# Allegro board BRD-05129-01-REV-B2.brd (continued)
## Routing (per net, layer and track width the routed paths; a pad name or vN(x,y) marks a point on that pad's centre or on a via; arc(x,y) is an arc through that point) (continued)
N1766806: length 1.6
  BOTTOM w0.203: R33.2 20.34,18.74 20.5,18.59 C37.1
N1766990: length 4.7
  TOP w0.203: v7(15.76,22.64) 15.76,23.86 16.56,24.66 17.1,24.66 Q21.2 17.35,25.03 17.31,25.07 R265.2
  BOTTOM w0.203: U6.7 v7(15.76,22.64)
N1767106: length 3.3
  BOTTOM w0.203: R32.2 17.14,20.38 17.59,19.93 C39.2 R30.2
  BOTTOM w0.254: R30.2 16.03,19.49 R31.1
N1767370: length 1.4
  BOTTOM w0.254: C319.2 23.19,18.59 R223.1
N2390901: length 3.5
  BOTTOM w0.13: R260.2 3.13,107.87 3.03,107.77 Q20.3 3.44,107.23 3.7,106.97 4.5,106.97 Q18.1
N2549814: length 1
  BOTTOM w0.13: C344.1 R264.2
N3548094: length 2.9
  BOTTOM w0.13: U38.35 29.38,93.06 28.36,92.04 R428.1
N3957555: length 2.5
  BOTTOM w0.13: R213.1 47.59,74.81 47.18,75.21 U37.24
N3957585: length 2.6
  BOTTOM w0.13: U37.22 47.38,76.21 47.9,75.69 R209.2
N3957595: length 2.8
  BOTTOM w0.13: C278.2 47.23,77.21 U37.20
N3957977: length 7.1
  BOTTOM w0.13: U43.54 61.98,86.91 61.22,86.15 60.83,86.15 60.34,85.66 59.93,85.66 59.44,85.17 59.44,84.88 C568.1 59.27,83.63 X13.1
N3957979: length 8.9
  BOTTOM w0.13: U43.53 62.38,86.82 61.34,85.78 60.97,85.78 60.53,85.33 60.26,85.33 60.15,85.22 C569.1 60.15,84.06 59.56,83.47 59.56,82.27 60.58,81.25 X13.3
N3958007: length 2.1
  BOTTOM w0.13: R468.1 64.78,96.63 U43.24
N3958011: length 2.3
  BOTTOM w0.13: R469.1 65.18,96.14 U43.25
N3958031: length 6.1
  BOTTOM w0.13: X12.3 47.07,70.65 C566.1 47.07,72.51 R467.1 46.25,73.33 45.51,73.33 44.88,73.96 44.88,74.51 U37.26
N3958033: length 9.1
  BOTTOM w0.13: X12.1 47.75,68.42 47.5,68.67 47.5,71.06 C567.1 47.96,71.52 R467.2 47.96,72.91 47.54,73.33 46.78,73.33 46.27,73.83 45.77,73.83 45.37,74.23 U37.25
N5304511: length 5.7
  BOTTOM w0.381: J24.9 66.86,103.33 C642.1
N5304817: length 4.2
  TOP w0.127: R537.2 58.48,95.45 60.19,93.74 60.19,93.49 60.42,93.26 U98.22
N5305693: length 1.5
  BOTTOM w0.13: R561.1 83.53,111.28 Q30.3
N5305711: length 4.2
  TOP w0.127: v1(68.08,95.03) 67.47,94.43 67.47,94.26 66.96,93.76 U98.10
  BOTTOM w0.13: R539.1 69.2,94.88 69.05,95.03 v1(68.08,95.03)
N5322338: length 5.3
  BOTTOM w0.381: C665.1 88.03,93.05 J25.P9_U
N5322486: length 3.9
  BOTTOM w0.13: R564.2 101.39,89.84 100.63,89.07 100.63,88.76 100.27,88.4 100.27,88.05 100.12,87.9 U99.22
N5323316: length 4.2
  BOTTOM w0.13: U99.10 93.55,88.4 92.83,89.13 92.83,89.31 92.07,90.07 91.46,90.07 91.05,89.65 R566.1
N5323550: length 0.9
  TOP w0.127: R578.1 Q32.3
N5323954: length 1.9
  TOP w0.127: R567.2 79.96,94 Q31.3 R577.1
N5327477: length 5.4
  BOTTOM w0.381: J25.P9_L 101.27,93.84 C687.1
N5327617: length 4.3
  TOP w0.127: R593.2 92.04,90.09 92.35,89.78 92.35,89.68 93.14,88.89 93.14,88.03 93.26,87.9 U101.22
N5328445: length 3.3
  TOP w0.127: U101.10 100.98,89.84 R595.1
N5328687: length 0.9
  TOP w0.127: R607.1 Q34.3
N5371142: length 2
  BOTTOM w0.13: R550.2 60.18,114.61 R551.1 Q29.3
N5372640: length 1.9
  TOP w0.127: R596.2 79.83,96.67 Q33.3 R606.1
N5400806: length 8.5
  BOTTOM w0.381: R520.1 128.51,84.08 130.38,82.22 132.51,82.22 134.03,83.74 J21.2
N5403476: length 2.6
  BOTTOM w0.381: R517.1 121.98,102.57 J19.2
N5403484: length 2.9
  BOTTOM w0.381: R518.1 117.9,103.57 J20.2
N5403540: length 7.3
  L03_SIG w0.254: v1(118.79,100.66) v1(118.79,101.67) 118.79,102.99 119.62,103.82 v1(119.62,105.19)
  BOTTOM w0.381: R517.2 v1(118.79,101.67) ; R518.2 v1(119.62,105.19) ; C601.1 v1(118.79,100.66)
N15688918: length 2
  TOP w0.127: DS10.2 v1(135.81,38.09)
  BOTTOM w0.13: DS10.2 v1(135.81,38.09)
N15743132: length 3.3
  TOP w0.203: v1(59.33,70.36) 59.09,70.6 R581.1
  BOTTOM w0.203: U100.7 58.65,71.04 v1(59.33,70.36)
N15988053: length 2.3
  BOTTOM w0.13: Q28.1 133.04,15.32 132.82,15.09 R532.1 R531.2
N15988135: length 0.8
  BOTTOM w0.13: R533.1 Q28.3
N15988139: length 1.6
  TOP w0.13: DS9.1 v1(134.29,16.56)
  BOTTOM w0.13: v1(134.29,16.56) 134.4,16.44 R533.2
N15991161: length 50.8
  L05_SIG w0.102: J23.1 28.75,17.16 28.75,20.37 29.13,20.75 29.13,22.78 28.44,23.46 28.44,35.17 v1(21.46,42.16)
  BOTTOM w0.13: R164.2 21.64,58.97 22.48,58.14 22.48,43.18 v1(21.46,42.16)
N15992386: length 7.2
  BOTTOM w0.381: J40.1 115.96,46.37 115.31,45.72 115.31,44.96 R660.2 115.27,44.9 R661.1 115.27,42.5 115.02,42.25 R662.1 Q44.3
N15992390: length 7.5
  L05_SIG w0.381: J41.1 117.19,28.3 v1(114.73,28.3)
  BOTTOM w0.381: R663.1 v1(114.73,28.3) 114.31,27.88 U113.5
N15992479: length 8.8
  TOP w0.254: C695.1 106.83,41.53 R624.1 106.85,41.04 v1(106.42,40.61) 106.6,40.43 U102.8
  L05_SIG w0.508: J26.1 106.02,40.61 v1(106.42,40.61)
  BOTTOM w0.381: R624.1 106.85,41.04 v1(106.42,40.61)
N15992497: length 8.8
  TOP w0.254: C702.1 106.83,58.42 R630.1 106.85,57.95 v1(106.4,57.5) 106.6,57.29 U103.8
  L05_SIG w0.508: J28.1 106.09,57.5 v1(106.4,57.5)
  BOTTOM w0.254: R630.1 106.85,57.95 v1(106.4,57.5)
N15992515: length 8.5
  TOP w0.254: C709.1 106.32,75.31 R636.1 106.35,74.64 v1(106.09,74.39) U104.8
  L05_SIG w0.508: v1(106.09,74.39) 103.78,74.39 J30.1
  BOTTOM w0.254: v1(106.09,74.39) 106.35,74.64 R636.1
N16064973: length 2.1
  BOTTOM w0.127: R528.1 R526.2
  BOTTOM w0.13: R526.2 73.05,23 R754.1
N16065039: length 2.6
  BOTTOM w0.381: Q24.1 76.33,20.91 C619.1 R528.2
N16065865: length 2.1
  BOTTOM w0.127: Q27.3 124.14,69.15 R527.2 R529.1
N16065931: length 2.6
  BOTTOM w0.381: Q25.1 126.67,70.17 C620.1 R529.2
N16074030: length 1.7
  BOTTOM w0.13: U19.5 R451.2
N16074034: length 1.9
  BOTTOM w0.13: U19.6 33.49,38.48 R450.2
N16074038: length 3
  BOTTOM w0.13: R449.2 31.42,38.73 31.42,39.67 32.01,40.27 U19.9
N16074042: length 2.1
  BOTTOM w0.13: R448.2 33.31,44.61 33.89,44.03 U19.20
N16074046: length 1.9
  BOTTOM w0.13: R447.2 34.2,44.38 34.29,44.28 U19.21
N16074090: length 2
  BOTTOM w0.13: R446.2 37.32,42.18 37.06,42.44 36.56,42.44 36.38,42.27 U19.27
N16074170: length 1.9
  BOTTOM w0.13: U91.2 70.77,80.33 70.55,80.12 R507.2
N16074248: length 1
  TOP w0.381: R54.2 29.27,22.24 ; C73.1 30.28,22.24
N16077585: length 1
  BOTTOM w0.13: R294.1 Q22.3
N16077589: length 2
  TOP w0.13: v1(2.25,37.84) 2.32,37.77 DS7.1
  BOTTOM w0.13: R294.2 2.44,37.66 v1(2.25,37.84)
N16077723: length 1.3
  BOTTOM w0.13: R295.1 3.72,33.96 Q23.3
N16077727: length 2
  TOP w0.13: v1(2.25,35.3) 2.32,35.23 DS8.1
  BOTTOM w0.13: v1(2.25,35.3) 2.44,35.12 R295.2
N16080552: length 1.2
  BOTTOM w0.13: Q6.3 R157.1
N16080556: length 2
  TOP w0.13: DS1.1 2.32,30.15 v1(2.25,30.22)
  BOTTOM w0.13: R157.2 2.44,30.04 v1(2.25,30.22)
N16080656: length 1
  BOTTOM w0.13: R254.1 Q17.3
N16080660: length 2
  TOP w0.13: v1(2.25,27.68) 2.32,27.61 DS6.1
  BOTTOM w0.13: R254.2 2.44,27.5 v1(2.25,27.68)
N16080760: length 1
  BOTTOM w0.13: R158.1 Q7.3
N16080764: length 2
  TOP w0.13: DS2.1 2.32,25.07 v1(2.25,25.14)
  BOTTOM w0.13: v1(2.25,25.14) 2.44,24.96 R158.2
N16080864: length 1
  BOTTOM w0.13: R159.1 Q8.3
N16080868: length 2
  TOP w0.13: DS3.1 2.32,22.53 v1(2.25,22.6)
  BOTTOM w0.13: v1(2.25,22.6) 2.44,22.42 R159.2
N16080968: length 1
  BOTTOM w0.13: R160.1 Q9.3
N16080972: length 2
  TOP w0.13: v1(2.25,20.06) 2.32,19.99 DS4.1
  BOTTOM w0.13: R160.2 2.44,19.88 v1(2.25,20.06)
N16081072: length 1
  BOTTOM w0.13: R161.1 Q10.3
N16081076: length 2
  TOP w0.13: DS5.1 2.32,17.45 v1(2.25,17.52)
  BOTTOM w0.13: v1(2.25,17.52) 2.44,17.34 R161.2
N16081750: length 1.5
  BOTTOM w0.13: U22.15 38.79,30.56 38.53,30.82 R66.1
N16081820: length 4
  TOP w0.127: X1.3 56.35,7.42 56.56,7.21 56.56,6.12 55.69,5.24 J4.4
N16081954: length 4.6
  TOP w0.254: 56.96,5.75 56.34,5.13 J4.5
  TOP w0.381: 56.96,5.75 57.85,6.64 L5.2 57.85,8.04 C88.2
N16082016: length 2.7
  TOP w0.127: v1(51.94,10.69) 52.36,11.11 R75.2
  BOTTOM w0.127: v1(51.94,10.69) 52.36,11.11 U24.14
N16082024: length 3.7
  TOP w0.127: R78.1 R74.2 v1(65.03,16.68)
  BOTTOM w0.13: U26.4 v1(65.03,16.68)
N16082026: length 14.6
  TOP w0.127: R76.2 v1(67.57,13.83)
  L03_SIG w0.102: v1(67.57,13.83) 67.07,13.33 61.31,13.33 59.68,14.96 v1(58.5,14.96)
  BOTTOM w0.127: U26.2 v1(67.57,13.83)
  BOTTOM w0.13: U24.62 v1(58.5,14.96)
N16082028: length 15.1
  TOP w0.13: R77.2 v1(68.84,13.83)
  L03_SIG w0.102: v1(59.24,14.46) 59.24,13.6 60.04,12.8 67.81,12.8 v1(68.84,13.83)
  BOTTOM w0.13: U26.1 v1(68.84,13.83) ; U24.63 v1(59.24,14.46)
N16082050: length 8.6
  TOP w0.127: R78.2 v1(66.3,13.83)
  L03_SIG w0.102: v1(62.25,15.01) 65.12,15.01 v1(66.3,13.83)
  BOTTOM w0.127: U26.3 v1(66.3,13.83)
  BOTTOM w0.13: U24.61 61.8,15.46 v1(62.25,15.01)
N16082060: length 6.1
  BOTTOM w0.13: C103.1 X2.1 60.35,9.53 59.35,9.53 58.36,10.52 U24.2
N16082074: length 9
  BOTTOM w0.13: U24.3 57.86,10.59 59.24,9.2 62.04,9.2 62.84,8.4 X2.3 C104.1
N16082098: length 2.7
  TOP w0.127: R79.2 56.31,13.2 v1(56,13.51)
  BOTTOM w0.13: U24.6 56.36,13.16 v1(56,13.51)
N16087534: length 0.9
  TOP w0.127: R274.1 C370.1
N16087546: length 0.9
  BOTTOM w0.13: R275.1 C371.1
N16095299: length 3.2
  TOP w0.381: U95.13 114.01,84.74 v1(113.58,85.18)
  BOTTOM w0.381: R534.1 114.01,84.74 v1(113.58,85.18)
N16189579:
  vias: v1(99.11,42.57) v1(100.38,42.57) v1(101.65,42.57)
N16189629:
  vias: v1(99.11,59.46) v1(101.65,59.46)
N16189705:
  vias: v1(97.18,73.81) v1(97.18,72.41) v1(101.34,72.49) v1(101.37,73.81)
N16192308: length 98.9
  TOP w0.127: Q37.1 v1(130.39,38.31)
  TOP w0.13: U104.7 106.59,74.08 v1(106.9,74.39) ; v1(107.41,57.5) 107.41,57.48 107.1,57.17 U103.7 ; U102.7 107.1,40.3 v1(107.41,40.61)
  L05_SIG w0.102: v1(107.41,40.61) 111.96,40.61 114.02,42.67 124.63,42.67 126.28,41.02 126.28,38.91 127.61,37.59 129.66,37.59 v1(130.39,38.31) 129.41,39.29 127.99,39.29 127.48,39.8 127.48,59.76 126.23,61.01 120.19,61.01 117.78,58.59 109.37,58.59 108.27,57.5 v1(107.41,57.5) 107.41,58.64 108.62,59.85 108.62,65.95 106.9,67.66 v1(106.9,74.39)
  BOTTOM w0.13: v1(107.41,40.61) R620.2 107.43,39.88 R623.1 C694.1
N16238907: length 2.8
  TOP w0.13: v1(113.58,94.23) 114.01,93.8 U95.8
  BOTTOM w0.13: R519.2 114.01,93.81 v1(113.58,94.23)
N17003721: length 3
  BOTTOM w0.254: R643.1 R642.1 126.41,44.08 126.41,44.8 126.44,44.83 TP41.1 126.44,45.38 126.41,45.41 R641.2
N17003765: length 4.3
  BOTTOM w0.254: R643.2 C722.1 124.75,42.09 124.75,42.09 U135.3
N17003879: length 4.4
  BOTTOM w0.254: R649.1 R648.1 118.19,59.14 117.94,58.88 TP43.1 R647.2
N17003923: length 4.2
  BOTTOM w0.254: R649.2 C731.1 U136.5
N17004020: length 3.1
  BOTTOM w0.254: R653.1 R652.1 131.25,63.62 TP45.1 131.83,63.62 131.84,63.62 R651.2
N17004081: length 4.3
  BOTTOM w0.254: R653.2 C742.1 129.2,61.7 U136.3
N17015726: length 5.1
  BOTTOM w0.254: U127.1 R63.2 74.34,48.82 R702.1
N17015844: length 5
  BOTTOM w0.254: U127.8 R64.2 74.32,54.89 R703.1
N17015909: length 5.1
  BOTTOM w0.254: R704.1 81.58,49.12 R58.2 U128.1
N17015913: length 23.1
  L12_SIG w0.254: v1(80.85,51.62) 80.52,51.96 80.03,51.96 79.68,51.61 79.68,48.41 78.52,47.26 75.98,47.26 70.94,42.21 67.64,42.21 v1(67.25,41.82)
  BOTTOM w0.254: v1(80.85,51.62) R704.2 U128.4 ; R740.1 v1(67.25,41.82)
N17016027: length 5
  BOTTOM w0.254: U128.8 R61.2 81.56,55.2 R705.1
N17016033: length 23
  L12_SIG w0.254: v1(67.25,42.96) 67.37,42.85 70.68,42.85 75.72,47.89 78.22,47.89 79.04,48.71 79.04,52.09 79.68,52.73 80.81,52.73 v1(80.85,52.77)
  BOTTOM w0.254: U128.5 R705.2 v1(80.85,52.77) ; R741.1 v1(67.25,42.96)
N17019057: length 5.1
  BOTTOM w0.254: U129.1 R707.2 74.34,57.77 R706.1
N17019061: length 12.4
  L12_SIG w0.254: v1(67.25,55.52) 69.34,57.62 72.27,57.62 73.62,58.96 v1(73.62,60.27)
  BOTTOM w0.254: v1(73.62,60.27) R706.2 U129.4 ; R742.1 v1(67.25,55.52)
N17019189: length 5
  BOTTOM w0.254: R709.1 74.32,63.84 R708.2 U129.8
N17019195: length 15.2
  L12_SIG w0.254: v1(67.25,54.38) 67.25,54.62 69.59,56.97 72.54,56.97 74.27,58.7 74.27,60.76 v1(73.62,61.41)
  BOTTOM w0.254: R743.1 v1(67.25,54.38) ; v1(73.62,61.41) R709.2 U129.5
N17019244: length 5.1
  BOTTOM w0.254: R710.1 81.58,58.07 R711.2 U130.1
N17019248: length 24.2
  L12_SIG w0.254: v1(80.85,60.57) 80.6,60.83 79.96,60.83 79.57,60.45 79.57,58.24 77.84,56.51 76.22,56.51 73.86,54.15 69.01,54.15 68.37,53.51 68.37,51.11 v1(67.25,49.99)
  BOTTOM w0.254: U130.4 R710.2 v1(80.85,60.57) ; R744.1 v1(67.25,49.99)
N17019376: length 5
  BOTTOM w0.254: U130.8 R712.2 81.56,64.15 R713.1
N17019382: length 23.8
  L12_SIG w0.254: v1(80.85,61.71) 80.83,61.69 79.9,61.69 78.89,60.68 78.89,58.57 77.46,57.14 75.95,57.14 73.6,54.78 68.74,54.78 67.74,53.78 67.74,51.62 v1(67.25,51.13)
  BOTTOM w0.254: R745.1 v1(67.25,51.13) ; U130.5 R713.2 v1(80.85,61.71)
N17020691: length 5.1
  BOTTOM w0.254: R714.1 74.34,66.71 R715.2 U131.1
N17020695: length 13.5
  L12_SIG w0.254: v1(67.25,63.69) 67.97,63.69 69.23,64.94 71.89,64.94 73.11,66.16 v1(73.11,69.21)
  BOTTOM w0.254: R746.1 v1(67.25,63.69) ; v1(73.11,69.21) 73.62,68.7 R714.2 U131.4
N17020826: length 5
  BOTTOM w0.254: U131.8 R716.2 74.32,72.79 R717.1
N17020832: length 16.1
  L12_SIG w0.254: v1(67.25,62.55) 67.69,62.99 68.17,62.99 69.49,64.31 72.16,64.31 73.74,65.89 73.74,69.72 v1(73.11,70.36)
  BOTTOM w0.254: v1(73.11,70.36) 73.62,70.86 R717.2 U131.5 ; R747.1 v1(67.25,62.55)
N17020881: length 5.1
  BOTTOM w0.254: R718.1 81.4,67.74 82.12,67.02 R719.2 U132.1
N17020885: length 24.4
  L12_SIG w0.254: v1(67.25,58.15) 68.25,59.15 68.25,60.96 68.98,61.69 72.41,61.69 75.87,65.15 78.23,65.15 79.73,66.65 79.73,69.26 80.23,69.77 80.6,69.77 v1(80.85,69.52)
  BOTTOM w0.254: R748.1 v1(67.25,58.15) ; U132.4 R718.2 v1(80.85,69.52)
N17021016: length 5
  BOTTOM w0.254: U132.8 R720.2 81.56,73.09 R721.1
N17021022: length 24
  L12_SIG w0.254: v1(80.85,70.66) 80.78,70.58 80.11,70.58 79.09,69.57 79.09,67 77.87,65.78 75.6,65.78 72.15,62.33 68.72,62.33 67.61,61.22 67.61,59.66 v1(67.25,59.3)
  BOTTOM w0.254: R749.1 v1(67.25,59.3) ; U132.5 R721.2 v1(80.85,70.66)
N17021071: length 5.1
  BOTTOM w0.254: U133.1 R723.2 74.34,39.87 R722.1
N17021075: length 12.4
  L12_SIG w0.254: v1(73.62,42.37) 73.62,40.53 71.84,38.76 67.68,38.76 v1(67.25,39.19)
  BOTTOM w0.254: R750.1 v1(67.25,39.19) ; U133.4 R722.2 v1(73.62,42.37)
N17021203: length 5
  BOTTOM w0.254: R725.1 74.32,45.95 R724.2 U133.8
N17021209: length 14.7
  L12_SIG w0.254: v1(73.62,43.52) 74.25,42.88 74.25,40.27 72.3,38.31 72.3,38.3 72.04,38.04 v1(67.25,38.04)
  BOTTOM w0.254: U133.5 R725.2 v1(73.62,43.52) ; R751.1 v1(67.25,38.04)
N17021264: length 5.1
  BOTTOM w0.254: R726.1 81.58,40.43 R727.2 U134.1
N17021268: length 22.9
  L12_SIG w0.254: v1(67.25,33.65) 67.5,33.9 71.9,33.9 75.89,37.89 77.82,37.89 79.52,39.59 79.52,42.87 79.8,43.15 80.64,43.15 v1(80.85,42.93)
  BOTTOM w0.254: U134.4 R726.2 v1(80.85,42.93) ; R752.1 v1(67.25,33.65)
N17021396: length 5
  BOTTOM w0.254: R729.1 81.56,46.51 R728.2 U134.8
N17021402: length 22.9
  L12_SIG w0.254: v1(80.85,44.08) 80.74,43.96 79.57,43.96 78.89,43.28 78.89,39.9 77.59,38.6 75.7,38.6 71.64,34.54 67.5,34.54 v1(67.25,34.79)
  BOTTOM w0.254: R753.1 v1(67.25,34.79) ; U134.5 R729.2 v1(80.85,44.08)
N17049267: length 4.7
  BOTTOM w0.13: U135.5 119.17,41.44 118.72,40.98 C758.1 R662.2
N17065894: length 11.4
  TOP w0.381: v1(69.58,41.62) 69.19,41.23 R737.2 R736.1 ; C809.1 70.23,36.87 v1(70.04,36.68)
  L10_SIG w0.381: v1(70.04,36.68) 68.63,38.1 68.63,40.66 69.58,41.61 v1(69.58,41.62)
  BOTTOM w0.381: v1(70.04,36.68) 70.23,36.87 C809.1 ; U137.5 v1(69.58,41.62)
N17098770: length 1.4
  TOP w0.127: Q37.3 DS10.1
N17140493: length 1.6
  BOTTOM w0.13: R754.2 72.11,22.49 71.99,22.36 Q26.3
N17244604: length 3.5
  BOTTOM w0.13: 113.33,41.66 R763.1 R762.2 Q43.3
N17444223: length 1.5
  TOP w0.13: D24.2 v1(38.19,17.31)
  BOTTOM w0.13: R267.2 v1(38.19,17.31)
N17444428: length 0.8
  TOP w0.13: D25.2 v1(45.13,17.4)

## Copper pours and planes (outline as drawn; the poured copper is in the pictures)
5V0_IN on TOP (solid shape): 27.25,28.14 27.25,25.22 27.22,25.21 27.07,25.09 26.99,24.91 26.99,24.86 21.18,24.86 19.78,26.26 19.78,28.44 20.05,28.71 26.68,28.71
5V0_IN on BOTTOM (solid shape): 113.98,89.49 113.98,88.58 113.72,88.32 112.59,88.32 112.38,88.52 112.38,89.65 112.42,89.68 113.79,89.68
5V0_IN on BOTTOM (solid shape): 6.71,73.9 6.71,71.13 6.58,71 4.77,71 4.77,72.44 4.76,72.6 4.61,72.75 4.61,74 4.8,74.2 6.41,74.2
5V0_IN on BOTTOM (solid shape): 71.75,19.12 71.75,17.28 71.09,17.28 71.01,17.26 70.93,17.22 69.69,17.22 69.46,17.45 69.46,18.74 70.1,19.37 71.49,19.37
5V0_IN on BOTTOM (solid shape): 31.39,82.18 31.39,81.32 31.6,81.11 33.43,81.11 33.72,80.82 36.08,80.82 36.13,80.76 36.13,79.58 35.9,79.35 30.21,79.35 29.93,79.63 29.93,82.25 29.98,82.3 31.27,82.3
5V0_IN on BOTTOM (solid shape): 66.56,25.14 66.56,24.73 67.53,23.76 68.19,23.76 68.7,24.28 68.7,25.49 68.95,25.49 68.95,25.49 68.95,24.37 69.18,24.15 69.18,23.52 68.84,23.18 66.63,23.18 65.86,23.95 64.6,23.95 64.43,24.11 64.43,25.77 65.93,25.77
5V0_IN on BOTTOM (solid shape): 125.25,72.22 125.25,70.75 125.07,70.56 124.44,70.56 124.26,70.48 124.19,70.3 124.19,69.81 122.87,69.81 122.87,72.27 125.2,72.27
5V0_IN on BOTTOM (solid shape): 27.25,28.09 27.25,25.25 27.22,25.23 27.05,25.11 26.97,24.92 26.96,24.88 21.02,24.88 19.24,26.66 19.24,27.04 18.81,27.57 18.81,27.59 18.79,27.71 18.73,27.82 18.73,28.56 18.86,28.69 26.65,28.69
5V0_IN on BOTTOM (solid shape): 9.9,44.56 8.03,44.56 7.9,44.69 7.52,44.69 7.44,44.8 7.44,45.43 7.35,45.52 7.27,45.58 7.18,45.58 6.43,45.58 6.38,45.58 6.36,45.57 6.23,45.48 6.18,45.33 6.18,44.75 6.12,44.69 6,44.68 5.66,44.68 5.54,44.8 5.54,46.35 5.91,46.73 9.9,46.73
5V0_IN on BOTTOM (solid shape): 5.25,54.15 5.25,53.99 5.21,53.91 5.19,53.83 5.19,53.13 5.21,53.04 5.25,52.96 5.25,52.6 5.61,52.24 6.63,52.24 6.78,52.09 6.78,51.99 6.28,51.99 6.1,51.92 6.03,51.74 6.03,51.23 6.1,51.05 6.28,50.97 6.78,50.97 6.78,49.14 6.65,49.02 4.01,49.02 4.01,52.17 4.09,52.24 4.17,52.24 4.19,52.27 4.72,52.27 4.92,52.47 4.92,53.01 4.95,53.07 4.95,53.13 4.95,54.2 4.97,54.22 5.18,54.22
5V0_IN on BOTTOM (solid shape): 29.45,83.53 29.45,77.83 29.18,77.56 26.56,77.56 26.51,77.61 26.51,78.89 26.63,79.01 27.48,79.01 27.7,79.22 27.7,79.93 28.18,79.93 28.18,79.88 28.19,79.82 28.21,79.77 28.24,79.73 28.27,79.68 28.31,79.65 28.35,79.61 28.4,79.59 28.45,79.57 28.51,79.56 28.56,79.56 28.61,79.57 28.66,79.58 28.71,79.6 28.76,79.63 28.8,79.66 28.84,79.7 28.87,79.75 28.89,79.8 28.91,79.85 28.91,79.9 28.91,79.96 28.91,80.01 28.89,80.06 28.87,80.11 28.84,80.15 28.8,80.19 28.76,80.23 28.71,80.26 28.66,80.28 28.61,80.29 28.56,80.3 28.51,80.3 28.45,80.29 28.4,80.27 28.35,80.24 28.31,80.21 28.27,80.18 28.24,80.13 28.21,80.09 28.19,80.04 28.18,79.98 28.18,79.93 27.7,79.93 27.7,81.05 27.99,81.34 27.99,83.17 27.87,83.29 27.83,83.31 27.78,83.33 27.73,83.34 27.71,83.34 26.66,83.34 26.66,83.51 27.46,83.51 27.46,83.52 27.77,83.52 27.91,83.66 27.96,83.66 27.96,83.71 28.01,83.76 29.22,83.76
5V0_IN on TOP: 43.38,93.26 43.38,91.18 42.74,90.55 39.75,90.55 39.32,90.98 39.32,92.45 39.52,92.65 40.64,92.65 41.27,93.29 43.35,93.29
5V0_IN on BOTTOM: 41.35,93.24 43.28,93.24 43.35,93.16 43.35,90.85 42.46,89.96 39.82,89.96 39.32,90.47 39.32,91.46 39.44,91.59 39.9,91.59 40.2,91.28 40.2,91.26 40.56,90.9 41.4,90.9 41.68,91.18 41.68,91.59 41.12,92.15 41.12,93.01
5V0_IN on L07_PWR: 1.27,114.05 2.35,116.65 4.95,117.73 60.93,117.72 60.93,116.45 83.54,116.45 83.54,117.72 86.65,117.72 86.65,117.21 87.25,115.77 88.68,115.18 101.39,115.18 102.83,115.77 103.42,117.21 103.42,117.72 135.05,117.71 137.65,116.63 138.73,114.03 138.73,65.91 90.88,65.91 89.71,64.74 89.71,28.06 87.7,26.06 87.7,1.28 4.95,1.27 2.35,2.35 1.27,4.95 ; 2 cut-outs
5V0_IN_SW on BOTTOM (solid shape): 21.4,23.99 25.84,23.99 26.35,23.48 26.35,21.21 25.89,20.74 23.61,20.74 22.79,19.92 22.75,19.91 22.72,19.92 22.64,19.97 22.54,19.99 22.03,19.99 21.93,19.97 21.85,19.92 21.78,19.89 21.71,19.92 21.62,19.97 21.53,19.99 21.02,19.99 20.84,19.92 20.76,19.74 20.76,19.25 20.58,19.25 20.43,19.4 20.43,20.9 19.62,21.71 19.62,23.36 18.86,24.12 17.72,24.12 17.59,24.25 17.97,24.63 19.24,24.63 19.37,24.75 20.64,24.75
5V0_RS485 on TOP (solid shape): 113.13,93.61 113.13,91.85 113.44,91.54 114.38,91.54 114.53,91.38 114.53,90.46 114.35,90.28 112.79,90.28 112.26,90.8 112.26,93.48 112.5,93.71 113.03,93.71
5V0_RS485 on BOTTOM (solid shape): 113.14,93.61 113.14,92 113.46,91.68 114.43,91.68 114.68,91.43 114.68,90.24 114.53,90.09 112.37,90.09 112.21,90.25 112.21,93.6 112.33,93.72 113.04,93.72
12V_IN on TOP (solid shape): 14.21,98.82 14.21,98.02 13.8,97.61 13.8,94.43 13.66,94.28 9.27,94.28 9.11,94.43 9.11,98.7 9.46,99.05 13.98,99.05
12V_IN on BOTTOM (solid shape): 14.67,24.5 15.81,24.5 16.45,23.86 17.46,23.86 17.46,23.61 15.94,23.61 14.29,21.96 10.03,21.96 9.8,22.19 9.8,24.38 10.05,24.63 14.54,24.63
12V_IN on BOTTOM: 74.67,22.77 74.69,22.74 75.3,22.74 75.61,22.44 77.08,22.44 77.13,22.49 77.13,23.4 76.83,23.71 76.83,24.19 76.72,24.29 76.19,24.29 75.96,24.52 75.96,25.16 75.71,25.41 74.82,25.41 74.67,25.26
12V_IN on L08_PWR: 1.27,116.3 1.91,117.11 2.73,117.75 26.41,117.75 26.41,31.8 28.52,29.69 28.52,16.86 28.16,16.51 1.27,16.51
12V_IN on L12_SIG: 77.85,25.01 77.85,3.27 75.87,1.29 14.63,1.29 9.75,6.17 9.75,24.63 10.31,25.19 19.15,25.19 21.81,22.53 21.81,18.97 31.24,9.55 63.32,9.55 69.62,15.85 69.62,25.19 70.28,25.85 77.01,25.85
12V_IN_JACK on TOP (solid shape): outline of 132 points within 13.25,95.26 20.97,109.27
12V_IN_JACK on BOTTOM (solid shape): outline of 106 points within 13.25,95.33 20.97,109.27
12V_IN_JACK on L03_SIG, L05_SIG, L12_SIG: 13.64,109.06 20.98,109.06 22.32,107.72 22.32,95.14 21.69,94.51 13.43,94.51 12.62,95.32 12.62,108.05
12V_IN_SOURCE on TOP (solid shape): 15.39,96.41 15.71,96.41 15.74,96.4 15.78,96.4 16.15,96.4 16.15,95.65 15.64,95.65 15.39,95.39 14.53,95.39 14.48,95.4 14.43,95.41 14.12,95.41 14.12,97.17 14.62,97.17
GND on TOP (solid shape): 7.59,44.14 7.59,42.92 7.37,42.7 6.26,42.7 6.02,42.94 6.02,44.13 6.25,44.36 7.37,44.36
GND on TOP (solid shape): 93.43,14.07 93.43,13.25 93.17,12.99 92.38,12.99 92.34,13 92.3,13 91.8,13 91.77,13 91.73,12.99 90.19,12.99 89.93,13.25 89.93,14.07 90.19,14.32 93.17,14.32
GND on TOP (solid shape): 104.69,72.06 104.83,72.06 104.89,72.04 104.94,72.03 105.24,72.03 105.3,72.04 105.36,72.06 105.83,72.06 105.89,72.04 105.94,72.03 107.03,72.03 107.18,71.88 107.18,69.9 106.98,69.69 105.89,69.69 104.84,70.74 103.44,70.74 103.23,70.95 101.88,70.95 101.88,71.95 102.76,72.84 103.91,72.84
GND on TOP (solid shape): 25.19,101.39 25.19,97.61 24.61,97.03 24.57,97.04 24.49,97.07 24.41,97.08 24.14,96.98 24.04,96.71 24.05,96.63 24.08,96.55 24.09,96.51 23.02,95.44 21.52,95.44 21.47,95.49 21.47,97.96 22.27,97.96 22.65,98.34 22.65,101.52 22.78,101.65 24.94,101.65
GND on TOP (solid shape): 105.2,55.17 105.33,55.17 105.37,55.15 105.41,55.14 105.45,55.14 105.75,55.14 105.79,55.14 105.83,55.15 105.87,55.17 106.28,55.17 106.29,55.16 106.36,55.16 106.41,55.14 106.45,55.14 107.57,55.14 107.71,55 107.71,52.87 107.56,52.72 106.11,52.72 106.01,52.82 106.01,52.83 106.04,52.91 106.05,53.01 106.04,53.09 106.01,53.17 106.01,53.19 106.01,53.4 105.55,53.85 103.9,53.85 103.69,54.06 102.36,54.06 102.36,55.67 102.63,55.95 104.42,55.95
GND on TOP (solid shape): 52.5,1.7 52.88,1.7 52.88,2.33 54.91,2.33 54.91,1.7 55.16,1.7 55.16,2.33 57.2,2.33 57.2,0.64 55.16,0.64 55.16,1.57 54.91,1.57 54.91,0.64 52.88,0.64 52.88,1.57 52.5,1.57 52.5,0.64 51.89,0.64 51.81,0.68 51.79,0.77 51.81,0.87 51.82,0.97 51.82,1.64 51.77,1.92 51.64,2.17 51.63,2.28 51.72,2.33 52.5,2.33
GND on TOP (solid shape): 105.2,38.28 105.33,38.28 105.37,38.26 105.41,38.25 105.45,38.25 105.75,38.25 105.79,38.25 105.83,38.26 105.87,38.28 106.33,38.28 106.37,38.26 106.4,38.25 106.46,38.22 106.49,38.15 106.49,38.15 106.85,37.78 107.22,38.15 107.25,38.22 107.32,38.25 107.58,38.25 107.84,37.99 107.84,37.35 107.14,36.65 106.04,36.65 105.73,36.96 103.97,36.96 103.77,37.17 102.36,37.17 102.36,38.78 102.63,39.06 104.42,39.06
GND on TOP (solid shape): outline of 229 points within 1.9,110.9 8.1,117.1
GND on TOP (solid shape): outline of 229 points within 1.9,1.9 8.1,8.1
GND on TOP (solid shape): outline of 229 points within 131.9,110.88 138.1,117.08
GND on TOP (solid shape): outline of 229 points within 131.9,1.91 138.1,8.12
GND on TOP (solid shape): outline of 238 points within 9.02,83.35 16.42,90.75
GND on TOP (solid shape): outline of 238 points within 9.02,29.7 16.42,37.1
GND on TOP (solid shape): outline of 238 points within 43.94,83.35 51.34,90.75
GND on TOP (solid shape): outline of 238 points within 43.94,29.7 51.34,37.1
GND on TOP (solid shape): outline of 238 points within 79.67,83.35 87.07,90.75
GND on TOP (solid shape): outline of 238 points within 79.67,29.7 87.07,37.1
GND on BOTTOM (solid shape): 111.94,89.56 111.94,88.47 111.69,88.22 110.55,88.22 110.37,88.4 110.37,89.62 110.43,89.68 111.82,89.68
GND on BOTTOM (solid shape): 42.59,13.42 42.34,13.17 42.34,11.9 42.21,11.77 40.48,11.77 40.41,11.85 40.41,12.92 40.79,13.3 40.81,13.3 40.94,13.42 40.94,15.71 41.07,15.84 42.59,15.84
GND on BOTTOM (solid shape): 4.43,72.39 4.43,70.8 4.59,70.64 4.59,69.45 4.4,69.26 2.82,69.26 2.64,69.43 2.64,70.76 2.77,70.87 2.82,71.04 2.82,72.44 4.38,72.44
GND on BOTTOM (solid shape): 4.77,62.58 4.77,59.25 4.59,59.08 2.76,59.08 2.49,58.8 2.49,55.98 2.66,55.8 4.09,55.8 4.19,55.7 4.19,52.62 4.06,52.5 3.53,52.5 3.35,52.32 3.35,49.07 3.3,49.02 1.06,49.02 0.68,49.4 0.68,62.53 0.86,62.71 4.64,62.71
GND on BOTTOM (solid shape): 74.36,28.67 74.36,26.28 71.01,26.28 70.65,26.64 70.65,27.83 70.52,27.96 69.08,27.96 68.92,27.8 68.92,26.51 68.9,26.48 68.42,26.48 68.29,26.61 68.29,27.75 68.16,27.88 65.93,27.88 65.75,27.7 65.75,26.46 65.67,26.38 64.33,26.38 64.27,26.43 64.27,28.49 64.85,29.06 73.96,29.06
GND on BOTTOM (solid shape): 25.87,87.72 25.87,85.59 25.52,85.23 24.33,85.23 24.2,85.11 24.2,83.66 24.35,83.51 25.65,83.51 25.67,83.48 25.67,83 25.54,82.87 24.4,82.87 24.27,82.74 24.27,80.19 24.64,79.83 25.13,79.83 25.13,79.29 25.2,79.11 25.38,79.04 25.87,79.04 25.87,77.68 25.81,77.62 23.48,77.62 22.9,78.2 22.9,86.35 24.3,87.75 25.85,87.75
GND on BOTTOM (solid shape): 40.12,84.5 40.12,82.96 40.1,82.93 37.96,82.93 37.61,83.29 37.61,84.48 37.48,84.61 36.03,84.61 35.88,84.45 35.88,83.16 35.86,83.13 35.37,83.13 35.25,83.26 35.25,84.4 35.12,84.53 32.57,84.53 32.2,84.17 32.2,83.68 31.67,83.68 31.49,83.6 31.41,83.42 31.41,82.93 30.05,82.93 29.99,82.99 29.99,85.32 30.57,85.9 38.72,85.9
GND on BOTTOM (solid shape): 59.99,64.54 62.53,64.54 62.75,64.32 62.75,53.74 62.75,53.72 62.75,44.51 62.75,43.34 62.75,33.16 62.51,32.91 59.64,32.91 59.61,32.94 59.61,32.94 58.97,32.94 58.97,32.94 58.97,37.73 58.99,37.75 58.97,37.77 58.97,46.75 58.99,46.77 58.97,46.79 58.97,64.3 59.23,64.56 59.99,64.56
GND on BOTTOM (solid shape): 26.46,19.96 26.46,18.08 26.46,18.08 26.46,17.89 26.21,17.64 25.05,17.64 25.04,17.65 24.96,17.68 24.87,17.69 24.78,17.68 24.7,17.65 24.69,17.64 24.54,17.64 24.45,17.73 24.45,17.93 24.48,18.01 24.57,18.03 24.61,18.03 25.59,18.03 25.77,18.1 25.84,18.28 25.84,19.6 25.77,19.78 25.59,19.85 24.61,19.85 24.56,19.85 24.51,19.83 24.45,19.83 24.45,19.93 24.74,20.22 26.21,20.22
GND on BOTTOM (solid shape): 5.79,44.41 5.86,44.38 5.93,44.37 6.18,44.37 6.25,44.38 6.31,44.41 6.37,44.38 6.43,44.37 6.68,44.37 6.75,44.38 6.81,44.41 6.87,44.38 6.93,44.37 7.68,44.37 7.73,44.38 7.78,44.39 7.81,44.4 7.9,44.31 9.84,44.31 10.11,44.05 10.11,42.93 9.83,42.66 7.78,42.66 7.73,42.68 7.68,42.68 5.93,42.68 5.88,42.68 5.83,42.66 5.56,42.66 5.49,42.59 5.49,41.11 4.71,41.11 4.66,41.11 4.61,41.1 4.52,41.11 4.47,41.19 4.47,44.11 4.78,44.42 5.78,44.42
GND on BOTTOM (solid shape): 64.42,77.63 64.42,76.3 64.41,76.29 64.38,76.23 64.37,76.16 64.37,75.86 64.38,75.81 64.4,75.76 64.38,75.71 64.37,75.66 64.37,75.36 64.38,75.31 64.4,75.26 64.38,75.21 64.37,75.16 64.37,74.36 64.38,74.3 64.41,74.24 64.42,74.22 64.42,74.07 64.67,73.82 66.84,73.82 66.96,73.7 66.96,73.61 66.44,73.61 66.26,73.54 66.19,73.36 66.19,72.85 66.26,72.67 66.44,72.59 66.96,72.59 66.96,72.22 66.78,72.04 63.87,72.04 62.64,73.27 62.64,74.22 62.65,74.23 62.67,74.29 62.68,74.36 62.68,74.66 62.68,74.71 62.66,74.76 62.68,74.81 62.68,74.86 62.68,75.16 62.68,75.21 62.66,75.26 62.68,75.31 62.68,75.36 62.68,75.66 62.68,75.71 62.66,75.76 62.68,75.81 62.68,75.86 62.68,76.15 62.76,76.23 62.76,77.63 62.89,77.76 64.29,77.76
GND on BOTTOM (solid shape): 55.55,78.35 55.55,76.98 55.54,76.97 55.51,76.91 55.5,76.84 55.5,76.54 55.51,76.49 55.52,76.44 55.51,76.39 55.5,76.34 55.5,76.04 55.51,75.99 55.52,75.94 55.51,75.89 55.5,75.84 55.5,75.04 55.51,74.97 55.54,74.91 55.55,74.9 55.55,74.8 55.8,74.54 57.33,74.54 57.33,73.97 57.4,73.79 57.58,73.71 58.09,73.71 58.09,73.01 56.23,73.01 56.15,73.04 56.07,73.05 55.99,73.04 55.91,73.01 55.63,73.01 54.83,73.81 54.83,73.81 54.76,73.88 53.92,73.88 53.77,74.04 53.77,74.9 53.78,74.91 53.8,74.97 53.81,75.04 53.81,75.34 53.81,75.39 53.79,75.44 53.81,75.49 53.81,75.54 53.81,75.84 53.81,75.89 53.79,75.94 53.81,75.99 53.81,76.04 53.81,76.34 53.81,76.39 53.79,76.44 53.81,76.49 53.81,76.54 53.81,76.87 53.9,76.96 53.9,78.35 54.02,78.48 55.42,78.48
GND on BOTTOM (solid shape): outline of 103 points within 118.03,5 124.2,17.97
GND on BOTTOM (solid shape): 26.35,30.38 26.35,29.33 26.22,29.2 18.86,29.2 17.84,28.18 17.84,27.55 17.27,27.55 17.09,27.47 17.02,27.29 17.02,26.78 17.09,26.6 17.27,26.53 17.84,26.53 17.84,26.02 18.03,25.83 18.03,25.01 15.94,25.01 15.78,24.85 14.68,24.85 14.65,24.88 14.54,24.88 14.25,25.17 9.9,25.17 9.34,24.61 9.34,22.04 9.93,21.45 14.29,21.45 14.39,21.34 14.38,21.31 14.36,21.25 14.35,21.19 14.35,20.68 14.38,20.57 14.45,20.48 14.5,20.41 14.47,20.33 14.43,20.25 14.41,20.17 14.41,19.79 14.42,19.74 14.43,19.69 14.43,19.61 14.37,19.56 14.24,19.47 14.2,19.32 14.2,18.81 14.27,18.63 14.45,18.55 14.73,18.55 14.82,18.49 14.81,18.39 14.26,17.77 11.76,17.77 8.45,21.08 8.45,27.71 8.89,28.14 15.44,28.14 18.21,30.91 25.82,30.91
GND on BOTTOM (solid shape): outline of 229 points within 1.9,110.9 8.1,117.1
GND on BOTTOM (solid shape): outline of 229 points within 1.9,1.9 8.1,8.1
GND on BOTTOM (solid shape): outline of 229 points within 131.9,110.88 138.1,117.08
GND on BOTTOM (solid shape): outline of 229 points within 131.9,1.91 138.1,8.11
GND on BOTTOM (solid shape): outline of 248 points within 9.02,83.35 16.42,90.75
GND on BOTTOM (solid shape): outline of 248 points within 9.02,29.7 16.42,37.1
GND on BOTTOM (solid shape): outline of 248 points within 43.94,83.35 51.34,90.75
GND on BOTTOM (solid shape): outline of 248 points within 43.94,29.7 51.34,37.1
GND on BOTTOM (solid shape): outline of 248 points within 79.67,83.35 87.07,90.75
GND on BOTTOM (solid shape): outline of 248 points within 79.67,29.7 87.07,37.1
GND on TOP: 89.61,65.32 92.88,65.32 92.88,29.23 91.89,28.24 91.89,20.52 92.5,19.91 97.28,19.91 97.99,20.62 104.82,20.62 104.82,19.35 105.08,19.1 111.48,19.1 112.29,18.28 112.29,13.99 112.24,13.93 109.37,13.93 108.41,14.9 105.8,14.9 105.27,15.43 105.27,16.23 104.69,16.81 96.95,16.81 96.19,17.57 90.45,17.57 86.76,21.26 86.76,28.95 89.2,31.39 89.2,64.92
GND on TOP: 102.9,86.54 104.1,86.54 104.56,86.08 104.56,83.6 104.22,83.27 102.86,83.27 102.86,86.5
GND on TOP: 110.01,61.56 113.38,61.56 113.38,59.97 113.1,59.68 110.18,59.68 110.01,59.86
GND on TOP: 128.98,29.51 123.21,29.51 122.55,30.17 122.55,33.07 122.6,33.07 126.41,36.88 138.05,36.88 139.37,35.56 139.37,19.5 138.53,18.66 130.12,18.66 129.49,19.3 129.49,29
GND on TOP: 63.51,45.91 63.51,43.34 63.45,43.29 62.33,43.29 62.15,43.47 62.15,45.57 62.5,45.92 63.5,45.92
GND on TOP: 109.5,78.45 112.87,78.45 112.87,76.86 112.59,76.58 109.68,76.58 109.5,76.75
GND on TOP: 63.51,54.08 63.51,51.51 63.45,51.45 62.33,51.45 62.15,51.63 62.15,53.74 62.5,54.09 63.5,54.09
GND on TOP: 12.62,99.64 13.93,99.64 14.08,99.79 14.08,100.95 13.7,101.33 12.66,101.33 12.56,101.23 12.56,99.7
GND on TOP: 110.01,44.67 113.38,44.67 113.38,43.07 113.1,42.79 110.18,42.79 110.01,42.97
GND on TOP: 63.51,62.25 63.51,59.68 63.45,59.62 62.33,59.62 62.15,59.8 62.15,61.9 62.5,62.25 63.5,62.25
GND on TOP: 124.2,17.77 124.2,12.75 122.75,11.3 122.75,5.28 122.09,4.62 118.79,4.62 118.26,5.15 118.26,10.31 119.11,11.16 119.11,17 119.93,17.83 124.15,17.83
GND on TOP: 66.7,98.95 67.88,98.95 67.96,98.87 67.96,97.53 65.7,97.53 65.7,98.07 65.71,98.08 66.31,98.08 66.56,98.33 66.56,98.81
GND on TOP: 63.51,37.74 63.51,35.18 63.45,35.12 62.33,35.12 62.15,35.3 62.15,37.4 62.5,37.75 63.5,37.75
GND on TOP: 43.4,93.8 43.4,95.12 42.78,95.73 38.64,95.73 38.43,95.52 38.43,93.83 39.17,93.09 40.47,93.09 41.18,93.8 43.39,93.8
GND on BOTTOM: 72.12,19.21 73.77,19.21 73.77,18.06 73.63,17.92 72.24,17.92 72.12,18.05
GND on BOTTOM: 89.61,65.32 93.16,65.32 94.03,64.46 94.03,29.6 92.19,27.76 92.19,20.47 92.62,20.05 96.25,20.05 98.64,22.44 109.56,22.44 109.9,22.78 112.31,22.78 112.44,22.65 112.44,13.51 112.31,13.38 110.13,13.38 109.52,13.99 104.8,13.99 103.63,15.16 103.63,15.34 102.15,16.81 96.95,16.81 95.99,17.77 88.93,17.77 86.79,19.91 86.79,28.98 89.2,31.39 89.2,64.92
GND on BOTTOM: 60.72,25.99 59.32,25.99 59.19,26.12 59.19,27.45 59.2,27.46 59.22,27.52 59.23,27.59 59.23,27.89 59.23,27.94 59.21,27.99 59.23,28.04 59.23,28.09 59.23,28.39 59.23,28.44 59.21,28.49 59.23,28.54 59.23,28.59 59.23,29.39 59.22,29.45 59.2,29.52 59.19,29.53 59.19,29.68 58.94,29.93 56.65,29.93 56.65,31.87 59.8,31.87 60.97,30.69 60.97,29.53 60.96,29.52 60.93,29.46 60.92,29.39 60.92,29.09 60.93,29.04 60.95,28.99 60.93,28.94 60.92,28.89 60.92,28.59 60.93,28.54 60.95,28.49 60.93,28.44 60.92,28.39 60.92,28.09 60.93,28.04 60.95,27.99 60.93,27.94 60.92,27.89 60.92,27.6 60.84,27.52 60.84,26.12
GND on BOTTOM: 128.85,29.33 123.39,29.33 122.55,30.17 122.55,35.45 123.23,36.13 125.64,36.13 126.38,36.88 138.05,36.88 139.37,35.56 139.37,19.5 138.53,18.66 130.12,18.66 129.49,19.3 129.49,28.7
GND on BOTTOM: 43.33,93.8 41.46,93.8 41.16,94.1 41.16,95.29 41.44,95.56 43.21,95.56 43.35,95.42 43.35,93.82
GND on BOTTOM: 90.4,86.98 90.4,83.21 90.27,83.08 88.41,83.08 88.06,83.42 88.06,84.88 88.57,85.38 88.57,87.09 88.77,87.3 90.08,87.3
GND on BOTTOM: 72.9,85.54 72.9,86.94 73.03,87.07 74.36,87.07 74.37,87.06 74.43,87.03 74.5,87.02 74.8,87.02 74.85,87.03 74.9,87.04 74.95,87.03 75,87.02 75.3,87.02 75.35,87.03 75.4,87.04 75.45,87.03 75.5,87.02 76.3,87.02 76.36,87.03 76.42,87.06 76.44,87.07 76.52,87.07 76.71,87.26 76.71,88.4 76.63,88.48 76.63,89.58 76.65,89.61 77.98,89.61 78.11,89.48 78.11,86.4 77.18,85.47 74.35,85.47 74.29,85.41 73.03,85.41
GND on BOTTOM: 80.42,5.13 72.31,5.13 70.61,6.83 70.61,9.32 69.87,10.05 67.86,10.05 67.23,10.69 67.23,13.2 67.43,13.41 68.83,13.41 69.31,13.89 72.34,13.89 75.46,10.77 80.03,10.77 81.45,9.35 81.45,6.15
GND on L02_GND: 139.37,4.96 138.1,1.91 135.05,0.65 108.59,0.65 108.59,0.64 86.98,0.64 4.95,0.63 1.9,1.9 0.64,4.95 0.64,114.05 1.9,117.1 4.95,118.36 61.57,118.36 61.57,117.08 82.9,117.08 82.9,118.35 87.29,118.35 87.29,117.21 87.53,116.42 88.18,115.9 88.18,114.63 90.14,114.63 90.14,115.81 99.56,115.81 99.56,114.55 102.13,114.55 102.13,115.95 101.99,115.95 102.57,116.46 102.79,117.21 102.79,118.35 135.05,118.35 138.1,117.08 139.37,114.03 ; 1 cut-out
GND on L04_GND, L06_GND, L09_GND, L11_GND: 139.37,4.96 138.1,1.91 135.05,0.65 4.95,0.63 1.9,1.9 0.64,4.95 0.64,114.05 1.9,117.1 4.95,118.36 61.57,118.36 61.57,117.08 82.9,117.08 82.9,118.35 87.29,118.35 87.29,117.21 87.53,116.42 88.18,115.9 88.18,114.63 90.14,114.63 90.14,115.81 99.56,115.81 99.56,114.55 102.13,114.55 102.13,115.95 101.99,115.95 102.57,116.46 102.79,117.21 102.79,118.35 135.05,118.35 138.1,117.08 139.37,114.03
GND on L05_SIG: 66.26,60.96 66.26,28.93 131.82,28.93 131.82,69.62 74.93,69.62
GND on L05_SIG: 73.17,12.85 66.24,19.78 66.24,21.28 64.82,22.7 55.44,22.7 53.56,24.58 53.56,26.74 51.18,29.13 45.89,29.13 39.54,35.48 38.1,35.48 37.18,36.39 36.32,36.39 35.99,36.06 35.99,35.05 37.46,33.57 39.65,33.57 41.3,31.92 41.3,29.87 43.43,27.73 50.14,27.73 51.43,26.44 51.43,22.37 55.62,18.18 61.57,18.18 69.01,10.74 71.7,10.74 73.17,12.21
GND on L10_SIG: 129.08,63.42 129.08,63.8 123.49,69.39 96.8,69.39 92.48,73.71 75.84,73.71 71.52,69.39 61.39,69.39 58.87,66.88 58.87,35.07 62.02,31.92 118.41,31.92 122.98,36.5 122.98,57.83 123.24,58.09 123.24,63.29 123.36,63.42
GND on L10_SIG: 11.65,54.05 11.65,51.18 12.62,50.21 17.04,50.21 18.21,51.38 20.21,51.38 22.22,49.38 22.22,46.6 28.15,40.67 29.38,40.67 32.18,37.87 35.54,37.87 35.83,37.57 35.83,34.8 36.34,34.29 37.45,34.29 37.83,34.67 37.83,40.85 35.27,43.41 32.49,43.41 31.42,44.48 31.42,45.64 28.5,48.56 26.16,48.56 21.38,53.34 17.45,53.34 16.73,54.05
GND on L12_SIG: 81.76,73.58 86.41,73.58 92.4,67.59 124.28,67.59 124.32,67.55 125.97,67.55 127.05,66.47 127.05,64.56 124.89,62.4 124.89,46.66 120.32,42.08 120.32,31.67 117.83,29.18 112.92,29.18 110.56,31.54 84.12,31.54 82.34,33.32 82.34,53.39 81.71,54.02 79.9,54.02 78.66,52.78 77.49,52.78 76.29,53.98 81.45,59.15 81.45,62.15 81.33,62.28 77.01,62.28 76.75,62.53 76.75,63.55 77.49,64.28 79.02,64.28 82.6,67.86 82.6,71.42 81.76,72.26
GND on L13_GND: 139.37,4.96 138.1,1.91 135.05,0.65 108.59,0.65 108.59,0.64 86.98,0.64 4.95,0.63 1.9,1.9 0.64,4.95 0.64,114.05 1.9,117.1 4.95,118.36 61.57,118.36 61.57,117.08 82.9,117.08 82.9,118.35 87.29,118.35 87.29,117.21 87.53,116.42 88.18,115.9 88.18,114.63 90.14,114.63 90.14,115.81 99.56,115.81 99.56,114.55 102.13,114.55 102.13,115.95 101.99,115.95 102.57,116.46 102.79,117.21 102.79,118.35 135.05,118.35 138.1,117.08 139.37,114.03
GND1_RS485 on TOP (solid shape): 111.79,93.67 111.79,90.96 111.67,90.84 110.51,90.84 110.34,91.02 110.34,93.51 110.55,93.72 111.74,93.72
GND1_RS485 on BOTTOM (solid shape): 111.84,93.61 111.84,90.15 111.78,90.09 110.37,90.09 110.17,90.29 110.17,93.52 110.31,93.67 111.78,93.67
GND1_RS485 on L03_SIG: 116.96,94.59 116.96,92.55 116.26,91.85 112.94,91.85 111.73,90.65 110.38,90.65 110.18,90.85 110.18,93.59 110.51,93.92 111.25,93.92 111.26,93.91 115.2,93.91 115.97,94.69 116.86,94.69
GND2_RS485 on TOP (solid shape): 111.81,81.07 111.68,80.95 110.54,80.95 110.41,81.07 110.41,84.25 110.54,84.37 111.81,84.37
GND2_RS485 on BOTTOM (solid shape): 111.93,84.12 111.93,81.71 111.81,81.58 110.41,81.58 110.41,84.25 110.54,84.37 111.68,84.37
(no net) on TOP: 111.81,84.37 111.81,81.07 111.68,80.95 110.54,80.95 110.41,81.07 110.41,84.25 110.54,84.37
(no net) on TOP: 57.7,18.08 57.7,16.3 57.5,16.09 57.5,14.76 57.96,14.3 57.96,13.57 57.69,13.31 56.72,13.31 56.13,13.9 56.13,18.03 56.3,18.21 57.58,18.21
(no net) on TOP: 104.25,65.86 101.88,65.86 101.35,65.32 97.96,65.32 97.23,66.06 97.23,69.67 101.07,69.67 101.07,67.27 101.45,66.9 104.26,66.9 104.38,66.79 104.38,65.98
(no net) on TOP: 102.47,86.55 102.47,83.41 102.44,83.38 101.56,83.38 101.13,83.81 101.13,84.19 100.63,84.69 100.63,85.07 100.82,85.26 101.03,85.26 101.27,85.51 101.27,86.33 101.49,86.55
(no net) on TOP: 116.8,82.62 115.05,82.62 114.97,82.69 114.97,84.41 114.35,85.03 114.35,86.87 114.5,87.01 115.44,87.01 115.68,86.78 115.68,85.48 116.83,84.33 116.83,82.65
(no net) on TOP: 106.67,61.44 106.67,60.66 106.61,60.6 105.78,60.6 105.33,60.16 105.33,57.23 105.7,56.86 105.7,55.44 105.28,55.44 105.17,55.56 105.17,56.47 104.55,57.08 104.55,60.73 105.26,61.44
(no net) on TOP: 113.03,84.43 112.34,84.43 112.23,84.32 112.23,80.45 112.28,80.39 113.64,80.39 113.91,80.67 113.91,82.22 113.83,82.3 113.44,82.3 113.1,82.64 113.1,84.35
(no net) on TOP: 102.36,36.56 105.45,36.56 105.76,36.25 105.76,35.67 105.71,35.59 105.7,35.5 105.7,34.12 102.5,34.12 102.18,34.44 102.18,35.25 102.36,35.43
(no net) on TOP: 63.96,54.12 64.61,54.12 64.97,53.77 65.1,53.77 65.39,53.48 65.39,51.92 64.94,51.46 64.04,51.46 63.92,51.59 63.92,54.08
(no net) on TOP: 112.23,79.99 113.49,79.99 113.66,79.82 113.66,79.05 113.36,78.75 112.41,78.75 112.23,78.93
(no net) on TOP: 109.06,77.07 109.06,78.5 108.89,78.67 106.83,78.67 106.57,78.41 106.57,77.54 106.65,77.45 107.75,77.45 108.14,77.07
(no net) on TOP: 59.74,16.56 59.74,19.6 59.61,19.73 58.59,19.73 58.34,19.48 58.34,16.56
(no net) on TOP: 102.18,53.45 105.25,53.45 105.76,52.94 105.76,52.56 105.71,52.48 105.7,52.39 105.7,51.01 102.5,51.01 102.18,51.33
(no net) on TOP: 117.7,5.25 117.7,10.94 118.31,11.55 118.31,16.96 118.11,17.17 113.46,17.17 113.15,16.86 113.15,12.31 112.11,11.27 112.11,4.57 112.57,4.11 116.56,4.11
(no net) on TOP: 111.59,80.44 111.59,79.12 111.45,78.98 110.28,78.98 110.05,79.21 110.05,80.31 110.27,80.53 111.51,80.53
(no net) on TOP: 105.25,72.33 105.25,73.68 104.82,74.12 104.82,77.05 105.27,77.5 106.1,77.5 106.16,77.55 106.16,78.43 105.99,78.6 105.03,78.6 104.05,77.62 104.05,73.97 104.66,73.36 104.66,72.44 104.76,72.33
(no net) on TOP: 106.67,44.55 106.67,43.77 106.61,43.71 105.78,43.71 105.33,43.26 105.33,40.34 105.7,39.97 105.7,38.55 105.28,38.55 105.17,38.67 105.17,39.07 104.24,40 104.24,42.34 104.52,42.62 104.52,43.81 105.36,44.65 106.57,44.65
(no net) on TOP: 102.63,55.95 104.42,55.95 105.2,55.17 105.33,55.17 105.4,55.15 105.45,55.14 105.75,55.14 105.8,55.15 105.87,55.17 106.28,55.17 106.29,55.16 107.56,55.16 107.71,55 107.71,52.87 107.56,52.72 106.11,52.72 106.01,52.82 106.01,53.4 105.55,53.85 103.9,53.85 103.69,54.06 102.36,54.06 102.36,55.67
(no net) on TOP: 90.1,16.12 93.23,16.12 93.48,15.86 93.48,15.01 93.23,14.75 90.1,14.75 89.84,15.01 89.84,15.86
(no net) on TOP: 13.98,99.05 9.46,99.05 9.11,98.7 9.11,94.43 9.27,94.28 13.66,94.28 13.8,94.43 13.8,97.61 14.21,98.02 14.21,98.82
(no net) on TOP: 63.96,62.29 64.77,62.29 65.41,61.65 65.41,60.01 65.03,59.63 64.04,59.63 63.92,59.75 63.92,62.24
(no net) on TOP: 98.62,32.48 98.62,37.51 101.52,37.51 101.52,33.83 102.15,33.2 105.2,33.2 105.2,32.48
(no net) on TOP: 104.74,70.34 101.67,70.34 101.67,68.23 101.99,67.9 105.22,67.9 105.25,67.93 105.25,69.83
(no net) on TOP: 118.1,82.64 117.45,82.64 117.33,82.76 117.33,84.48 116.69,85.12 116.69,86.59 116.95,86.85 117.54,86.85 118.13,86.27 118.13,82.67
(no net) on TOP: 20.05,28.71 26.68,28.71 27.25,28.14 27.25,24.86 21.18,24.86 19.78,26.26 19.78,28.44
(no net) on TOP: 102.07,42.81 102.07,39.82 98.62,39.82 98.62,42.71 98.88,42.97 101.92,42.97
(no net) on TOP: 111.74,93.72 110.55,93.72 110.34,93.51 110.34,91.02 110.51,90.84 111.67,90.84 111.79,90.96 111.79,93.67
(no net) on TOP: 102.07,59.7 102.07,56.71 98.62,56.71 98.62,59.61 98.88,59.86 101.92,59.86
(no net) on TOP: 113.03,93.71 112.5,93.71 112.26,93.48 112.26,90.8 112.79,90.28 114.35,90.28 114.53,90.46 114.53,91.38 114.38,91.54 113.44,91.54 113.13,91.85 113.13,93.61
(no net) on TOP: 101.88,70.95 103.23,70.95 103.44,70.74 104.84,70.74 105.89,69.69 106.98,69.69 107.18,69.9 107.18,71.88 107,72.06 104.69,72.06 103.91,72.84 102.76,72.84 101.88,71.95
(no net) on TOP: 48.43,12.24 46.78,12.24 46.53,11.98 46.53,10.46 46.66,10.33 47.29,10.33 47.92,10.97 48.43,10.97
(no net) on TOP: 23.02,95.44 21.52,95.44 21.47,95.49 21.47,97.96 22.27,97.96 22.65,98.34 22.65,101.52 22.78,101.65 24.94,101.65 25.19,101.39 25.19,97.61
(no net) on TOP: 50.19,8.23 53.31,8.23 53.51,8.43 53.51,9.57 53.26,9.83 50.85,9.83 50.19,9.16
(no net) on TOP: 50.34,3.22 59.76,3.22 59.76,0.64 50.34,0.64
(no net) on TOP: 20.84,95.26 20.97,95.4 20.97,105.17 20.97,105.17 20.97,108.92 20.62,109.27 14.02,109.27 13.25,108.5 13.25,102.99 14.9,101.34 17.87,101.34 18.08,101.14 18.08,97.07 17.57,96.57 16.4,96.57 16.4,95.39 16.53,95.26
(no net) on TOP: 108.64,60.18 108.26,60.56 107.16,60.56 107.08,60.65 107.08,61.52 107.34,61.78 109.4,61.78 109.57,61.61 109.57,60.18
(no net) on TOP: 64.94,35.25 63.92,35.25 63.92,37.74 64.84,37.74 65.44,37.15 65.44,35.75
(no net) on TOP: 98.62,49.2 98.62,54.4 101.39,54.4 101.77,54.02 101.77,50.47 101.88,50.36 104.8,50.36 105.03,50.14 105.03,49.2 104.77,48.94 98.88,48.94
(no net) on TOP: 113.93,95.58 113.93,96.98 113.76,97.15 112.88,97.15 112.64,96.91 112.64,95.67 112.83,95.49 113.84,95.49
(no net) on TOP: 63.92,45.91 63.92,43.42 64.04,43.29 64.66,43.29 64.76,43.39 65.02,43.39 65.4,43.77 65.4,45.37 64.82,45.95 63.96,45.95
(no net) on TOP: 6.02,44.13 6.02,42.94 6.26,42.7 7.37,42.7 7.59,42.92 7.59,44.14 7.37,44.36 6.25,44.36
(no net) on TOP: 114.35,96.37 114.35,95.59 113.93,95.16 113.93,94.35 114.17,94.11 115.01,94.11 115.24,94.33 115.24,95.26 115.49,95.51 115.49,96.37 115.35,96.51 114.5,96.51
(no net) on TOP: 92.55,83.92 92.76,84.12 92.76,84.88 92.63,85.01 91.61,85.01 91.49,84.88 91.49,83.99 91.56,83.92
(no net) on TOP: 53.89,3.48 53.89,5.63 54.15,5.89 54.15,7.16 54.4,7.41 54.4,7.92 54.66,8.17 55.42,8.17 55.55,8.3 55.55,9.19 55.42,9.32 54.53,9.32 53.77,8.56 53.77,7.79 53.64,7.67 52.62,7.67 52.62,6.52 53.51,5.63 53.51,3.48
(no net) on TOP: 108.64,43.29 108.26,43.67 107.16,43.67 107.08,43.75 107.08,44.63 107.34,44.88 109.4,44.88 109.57,44.71 109.57,43.29
(no net) on TOP: 102.63,39.06 104.42,39.06 105.2,38.28 105.33,38.28 105.4,38.26 105.45,38.25 105.75,38.25 105.8,38.26 105.87,38.28 107.56,38.28 107.84,37.99 107.84,37.35 107.14,36.65 106.04,36.65 105.73,36.96 103.97,36.96 103.77,37.17 102.36,37.17 102.36,38.78
(no net) on TOP: 96.57,72.16 96.57,73.91 96.74,74.09 101.6,74.09 101.7,73.99 101.7,72.36 101.16,71.83 96.9,71.83
(no net) on TOP: 90.19,14.32 93.17,14.32 93.43,14.07 93.43,13.25 93.17,12.99 90.19,12.99 89.93,13.25 89.93,14.07
(no net) on TOP: 15.64,95.65 15.39,95.39 14.12,95.39 14.12,97.17 14.62,97.17 15.39,96.41 16.26,96.41 16.26,95.77 16.13,95.65
(no net) on BOTTOM: 17.46,23.61 15.94,23.61 14.29,21.96 10.03,21.96 9.8,22.19 9.8,24.38 10.05,24.63 14.54,24.63 14.67,24.5 15.81,24.5 16.45,23.86 17.46,23.86
(no net) on BOTTOM: 26.35,30.38 26.35,29.33 26.22,29.2 18.86,29.2 17.84,28.18 17.84,26.02 18.1,25.77 18.1,25.01 15.94,25.01 15.78,24.85 14.57,24.85 14.25,25.17 9.9,25.17 9.34,24.61 9.34,22.04 9.93,21.45 14.29,21.45 14.54,21.2 15.05,21.2 15.05,20.52 14.99,20.47 14.68,20.47 14.54,20.32 14.54,19.57 14.65,19.46 14.99,19.46 15.05,19.4 15.05,18.66 14.26,17.77 11.76,17.77 8.45,21.08 8.45,27.71 8.89,28.14 15.44,28.14 18.21,30.91 25.82,30.91
(no net) on BOTTOM: 62.13,78.01 60.73,78.01 60.1,77.38 60.1,75.16 61.37,75.16 61.37,75.6 61.5,75.73 61.55,75.8 61.68,75.87 61.73,75.87 62.38,75.87 62.38,77.76
(no net) on BOTTOM: 33.72,80.82 33.43,81.11 31.6,81.11 31.39,81.32 31.39,82.18 31.27,82.3 29.98,82.3 29.93,82.25 29.93,79.63 30.21,79.35 35.9,79.35 36.13,79.58 36.13,80.76 36.08,80.82
(no net) on BOTTOM: 75.19,88.87 74.81,88.49 74.81,88.15 74.76,88.07 74.74,87.98 74.74,87.32 73.67,87.32 73.54,87.45 72.97,87.45 72.97,89.88 73.33,90.24 73.33,91.23 73.83,91.74 74.98,91.74 75.19,91.53
(no net) on BOTTOM: 5.48,56.23 8.43,56.23 8.43,58.09 9.32,58.97 9.32,61.01 9.06,61.26 8.17,61.26 8.05,61.39 8.05,62.33 7.79,62.58 5.56,62.58 5.41,62.43 5.41,56.31
(no net) on BOTTOM: 4.73,76.82 4.73,78.38 4.6,78.51 4.6,79.84 4.76,80 6.43,80 6.59,79.85 6.59,76.88 6.49,76.79 4.77,76.79
(no net) on BOTTOM: 56.43,56.68 57.93,56.68 58.71,55.9 58.71,54.88 56.73,54.88 56.28,55.33 56.28,56.53
(no net) on BOTTOM: 111.93,81.71 111.93,84.12 111.68,84.37 110.54,84.37 110.41,84.25 110.41,81.58 111.81,81.58
(no net) on BOTTOM: 110.17,93.52 110.17,90.29 110.37,90.09 111.78,90.09 111.84,90.15 111.84,93.61 111.78,93.67 110.31,93.67
(no net) on BOTTOM: 4.76,71 4.76,72.6 4.61,72.75 4.61,74 4.8,74.2 6.41,74.2 6.71,73.9 6.71,71.13 6.58,71
(no net) on BOTTOM: 124.95,69.83 124.95,70.44 125.25,70.75 125.25,72.22 125.2,72.27 122.87,72.27 122.87,69.81 124.92,69.81
(no net) on BOTTOM: 53.51,76.57 53.51,78.48 53.26,78.73 51.86,78.73 51.23,78.1 51.23,75.94 51.36,75.81 52.37,75.81 52.5,75.94 52.5,76.32 52.75,76.57
(no net) on BOTTOM: 70.91,62.44 72.54,62.44 72.79,62.19 72.79,60.65 72.68,60.54 71.18,60.54 70.89,60.82 70.89,61.25 70.91,61.3 70.91,61.35
(no net) on BOTTOM: 106.75,68.93 108.31,68.93 108.97,68.27 108.97,67.1 108.86,66.99 108.44,66.99 108.29,67.15 108.29,67.87 108.01,68.15 106.95,68.15 106.75,68.35
(no net) on BOTTOM: 20.53,95.33 20.97,95.77 20.97,105.17 20.97,105.17 20.97,108.92 20.62,109.27 14.02,109.27 13.25,108.5 13.25,101.9 14.05,101.11 17.93,101.11 18.31,100.73 18.31,98.57 17.07,97.33 16.07,97.33 15.9,97.16 15.9,95.33
(no net) on BOTTOM: 103.77,54.25 105.15,52.87 105.15,51.67 105.02,51.54 102.4,51.54 101.88,52.05 98.88,52.05 98.88,54.55 99.11,54.78 100.88,54.78 101.42,54.25
(no net) on BOTTOM: 18.86,24.12 17.72,24.12 17.59,24.25 17.97,24.63 19.24,24.63 19.37,24.75 20.64,24.75 21.4,23.99 25.84,23.99 26.35,23.48 26.35,21.21 25.89,20.74 23.61,20.74 22.7,19.83 22.7,19.25 20.58,19.25 20.43,19.4 20.43,20.9 19.62,21.71 19.62,23.36
(no net) on BOTTOM: 9.9,44.56 8.03,44.56 7.9,44.69 7.52,44.69 7.44,44.8 7.44,45.43 7.27,45.58 6.38,45.58 6.25,45.45 6.25,44.82 6.12,44.69 5.92,44.67 5.66,44.67 5.54,44.8 5.54,46.35 5.91,46.73 9.9,46.73
(no net) on BOTTOM: 107.26,51.45 107.26,52.04 108.81,52.04 109.47,51.38 109.47,50.21 109.37,50.1 108.95,50.1 108.8,50.26 108.8,50.97 108.51,51.26 107.46,51.26
(no net) on BOTTOM: 106.3,35.06 106.87,35.06 106.87,33.47 106.75,33.35 106.35,33.35 106.21,33.5 106.21,34.97
(no net) on BOTTOM: 56.44,39.88 58.39,39.88 58.71,39.56 58.71,38.52 57.26,38.52 57.18,38.51 57.11,38.48 57.09,38.47 56.81,38.19 56.41,38.19 56.28,38.32 56.28,39.73
(no net) on BOTTOM: 55.8,76.57 55.8,77.72 55.93,77.84 55.93,78.61 56.18,78.86 59.1,78.86 59.59,78.37 59.59,76.37 59.34,76.12 57.52,76.12 57.07,76.57
(no net) on BOTTOM: 70.1,19.37 71.49,19.37 71.75,19.12 71.75,17.25 71.72,17.22 69.69,17.22 69.46,17.45 69.46,18.74
(no net) on BOTTOM: 3.35,49.07 3.35,52.32 3.53,52.5 4.06,52.5 4.19,52.62 4.19,55.7 4.09,55.8 2.66,55.8 2.49,55.98 2.49,58.8 2.76,59.08 4.59,59.08 4.77,59.25 4.77,62.58 4.64,62.71 0.86,62.71 0.68,62.53 0.68,49.4 1.06,49.02 3.3,49.02
(no net) on BOTTOM: 53.9,78.35 53.9,76.96 53.77,76.83 53.77,74.04 53.92,73.88 54.76,73.88 54.83,73.81 54.83,73.81 55.63,73.01 58.09,73.01 58.09,74.54 55.8,74.54 55.55,74.8 55.55,78.35 55.42,78.48 54.02,78.48
(no net) on BOTTOM: 112.59,88.32 113.72,88.32 113.98,88.58 113.98,89.49 113.79,89.68 112.42,89.68 112.38,89.65 112.38,88.52
(no net) on BOTTOM: 112.39,84.14 112.99,84.14 113.1,84.04 113.1,82.63 113.45,82.28 113.74,82.28 113.84,82.18 113.84,80.66 113.73,80.55 112.53,80.55 112.35,80.73 112.35,84.1 112.39,84.14
(no net) on BOTTOM: 110.55,88.22 111.69,88.22 111.94,88.47 111.94,89.56 111.82,89.68 110.43,89.68 110.37,89.62 110.37,88.4
(no net) on BOTTOM: 26.46,18.08 26.46,18.08 26.46,17.89 26.21,17.64 24.54,17.64 24.45,17.73 24.45,19.93 24.74,20.22 26.21,20.22 26.46,19.96
(no net) on BOTTOM: 7.32,39.46 7.44,39.34 10.01,39.34 10.19,39.51 10.19,42.05 9.98,42.26 7.44,42.26 7.32,42.13
